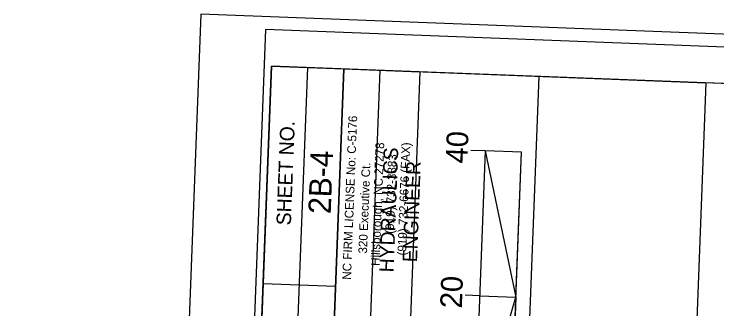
# Model space of a CAD drawing. Extents: x 2097431 to 2097897, y 685861 to 686794.
# Drawn here: x 2097431.2 to 2097528.3, y 686654.7 to 686695.3 of the extents above; entities that cross this region are included whole.
import ezdxf

# ---------------------------------------------------------------- set-up
doc = ezdxf.new("R2010")
doc.units = 0
for name, color, linetype in [('Scratch_Level_5', 7, 'Continuous'), ('Sheet Block Title CELL', 7, 'Continuous'), ('Sheet Data Field CELL', 7, 'Continuous'), ('Sheet Plan And Profile CELL', 7, 'Continuous'), ('Sheet Plot Border Inside CELL', 7, 'Continuous'), ('Sheet Plot Border Outside CELL', 7, 'Continuous'), ('Sheet Profile CELL', 7, 'Continuous'), ('Sheet Title CELL', 7, 'Continuous')]:
    doc.layers.add(name, color=color, linetype=linetype)

msp = doc.modelspace()

# ---------------------------------------------------------------- linework, layer by layer
at = {"layer": 'Scratch_Level_5'}
msp.add_lwpolyline([(2097443.756, 686088.61), (2097699.444, 686078.804), (2097722.438, 686678.363), (2097503.654, 686686.754), (2097500.587, 686606.792), (2097463.684, 686608.208)], close=True, dxfattribs=at)
at = {"layer": 'Sheet Block Title CELL'}
msp.add_lwpolyline([(2097473.696, 686607.824), (2097476.763, 686687.788), (2097487.258, 686687.386), (2097484.191, 686607.421)], close=True, dxfattribs=at)
at = {"layer": 'Sheet Data Field CELL'}
for p, q in [((2097496.272, 686676.469), (2097494.268, 686676.546)), ((2097495.5, 686656.484), (2097493.507, 686656.561))]:
    msp.add_line(p, q, dxfattribs=at)
at = {"layer": 'Sheet Plan And Profile CELL'}
for p, q in [((2097468.7, 686608.015), (2097471.767, 686687.976)), ((2097473.696, 686607.824), (2097476.763, 686687.785)), ((2097465.621, 686658.19), (2097475.613, 686657.807))]:
    msp.add_line(p, q, dxfattribs=at)
for points in [[(2097466.75, 686688.169), (2097443.756, 686088.61), (2097863.448, 686072.514), (2097886.442, 686672.073)], [(2097463.684, 686608.208), (2097466.75, 686688.169), (2097476.763, 686687.785), (2097473.696, 686607.824)], [(2097480.226, 686647.623), (2097481.759, 686687.593), (2097526.726, 686685.869), (2097525.193, 686645.898)]]:
    msp.add_lwpolyline(points, close=True, dxfattribs=at)
at = {"layer": 'Sheet Plot Border Inside CELL'}
msp.add_lwpolyline([(2097862.106, 686010.92), (2097887.653, 686677.03), (2097465.923, 686693.204), (2097440.376, 686027.094)], close=True, dxfattribs=at)
at = {"layer": 'Sheet Plot Border Outside CELL'}
msp.add_lwpolyline([(2097870.881, 686005.38), (2097896.695, 686678.485), (2097457.018, 686695.347), (2097431.204, 686022.242)], close=True, dxfattribs=at)
at = {"layer": 'Sheet Profile CELL'}
for p, q in [((2097468.7, 686608.015), (2097471.767, 686687.976)), ((2097465.621, 686658.19), (2097475.613, 686657.807))]:
    msp.add_line(p, q, dxfattribs=at)
for points in [[(2097466.75, 686688.169), (2097443.756, 686088.61), (2097863.448, 686072.514), (2097886.442, 686672.073)], [(2097463.684, 686608.208), (2097466.75, 686688.169), (2097476.763, 686687.785), (2097473.696, 686607.824)]]:
    msp.add_lwpolyline(points, close=True, dxfattribs=at)
at = {"layer": 'Sheet Title CELL'}
for p, q in [((2097496.271, 686676.464), (2097493.972, 686616.508)), ((2097496.271, 686676.464), (2097494.273, 686676.541)), ((2097501.273, 686676.272), (2097496.271, 686676.464)), ((2097498.968, 686616.316), (2097501.273, 686676.272)), ((2097495.505, 686656.479), (2097493.511, 686656.555)), ((2097495.505, 686656.479), (2097500.501, 686656.287))]:
    msp.add_line(p, q, dxfattribs=at)
for points in [[(2097496.271, 686676.464), (2097500.501, 686656.287), (2097501.273, 686676.272)], [(2097494.743, 686636.493), (2097500.501, 686656.287), (2097499.74, 686636.302)]]:
    msp.add_lwpolyline(points, close=True, dxfattribs=at)

# ---------------------------------------------------------------- texts
at = {"layer": 'Sheet Block Title CELL'}
for s, p in [('NC FIRM LICENSE No: C-5176', (2097477.727, 686658.672)), ('Hillsborough, NC 27278', (2097481.677, 686660.581)), ('(919) 732-6676 (FAX)', (2097485.336, 686662.02)), ('(919) 732-3883', (2097483.649, 686665.025)), ('320 Executive Ct.', (2097479.94, 686662.283))]:
    msp.add_text(s, height=1.20035, rotation=87.8037, dxfattribs=at).set_placement(p)
at = {"layer": 'Sheet Data Field CELL'}
for s, height, p in [('40', 3, (2097493.797, 686674.69)), ('2B-4', 3.1, (2097474.928, 686667.721)), ('20', 3, (2097493.035, 686654.704))]:
    msp.add_text(s, height=height, rotation=87.8037, dxfattribs=at).set_placement(p)
at = {"layer": 'Sheet Plan And Profile CELL'}
for s, p in [('SHEET NO.', (2097469.429, 686666.17)), ('HYDRAULICS', (2097483.611, 686659.682)), ('ENGINEER', (2097486.847, 686661.079))]:
    msp.add_text(s, height=2, rotation=87.8037, dxfattribs=at).set_placement(p)
at = {"layer": 'Sheet Profile CELL'}
msp.add_text('SHEET NO.', height=2, rotation=87.8037, dxfattribs=at).set_placement((2097469.424, 686666.175))

doc.saveas('drawing.dxf')
